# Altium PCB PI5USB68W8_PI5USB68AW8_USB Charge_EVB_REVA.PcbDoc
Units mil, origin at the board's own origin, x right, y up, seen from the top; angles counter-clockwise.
Board outline 2300 x 1200 mil, 4 copper layers (Top Layer, InternalPlane1, InternalPlane2, Bottom Layer); 16 components, 9 nets, 48 pads, 13 vias.
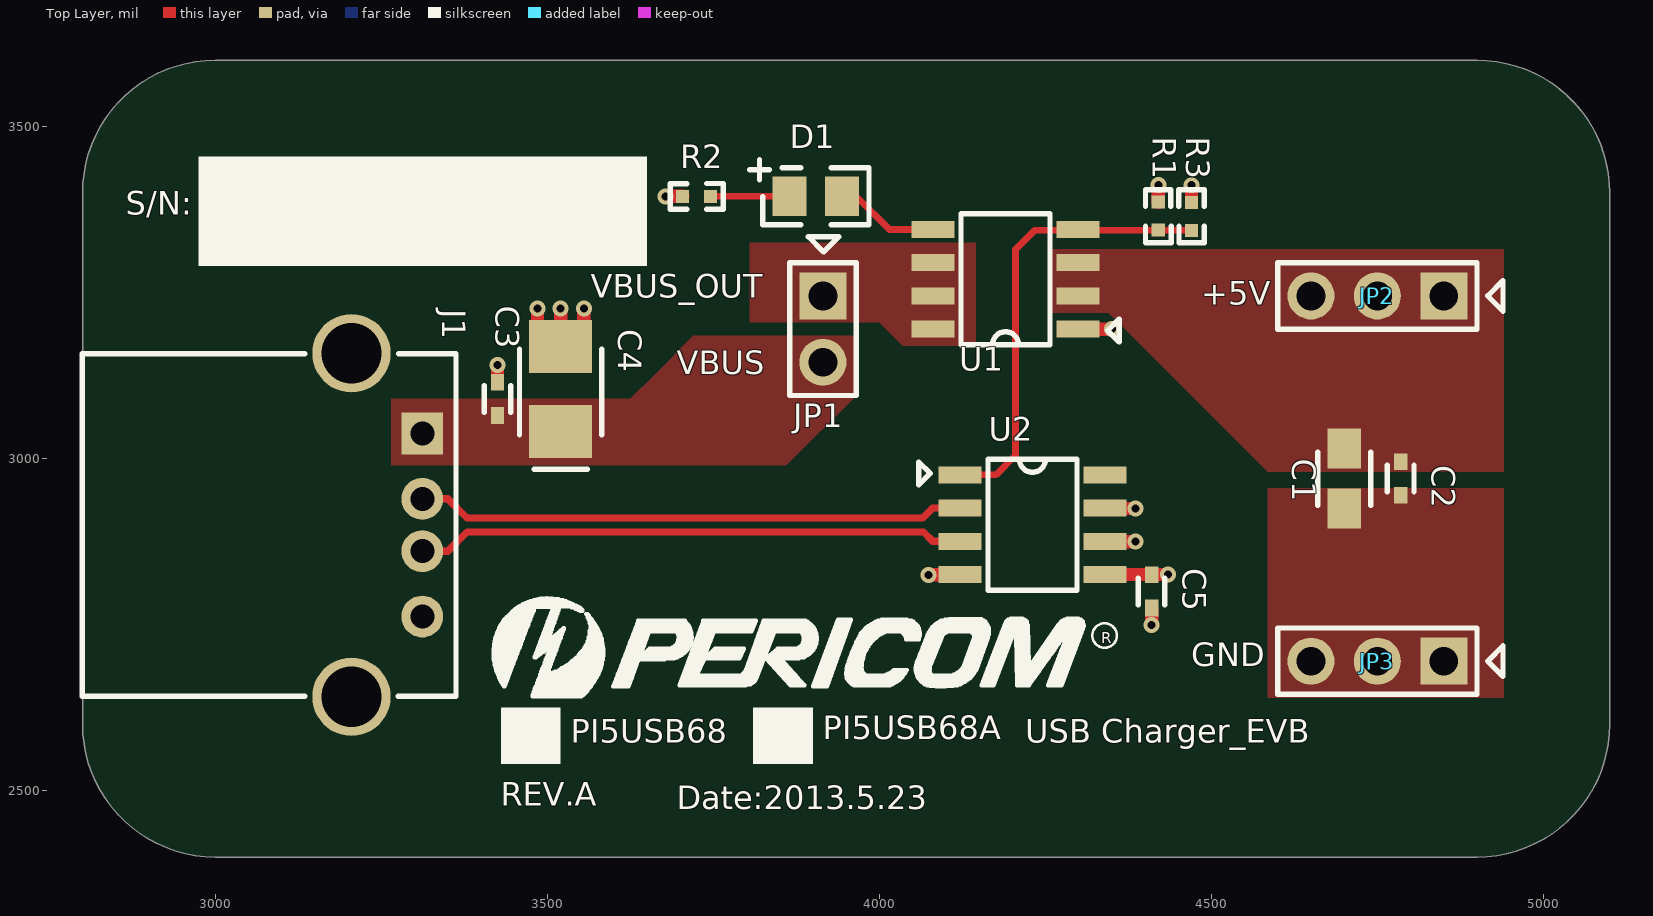
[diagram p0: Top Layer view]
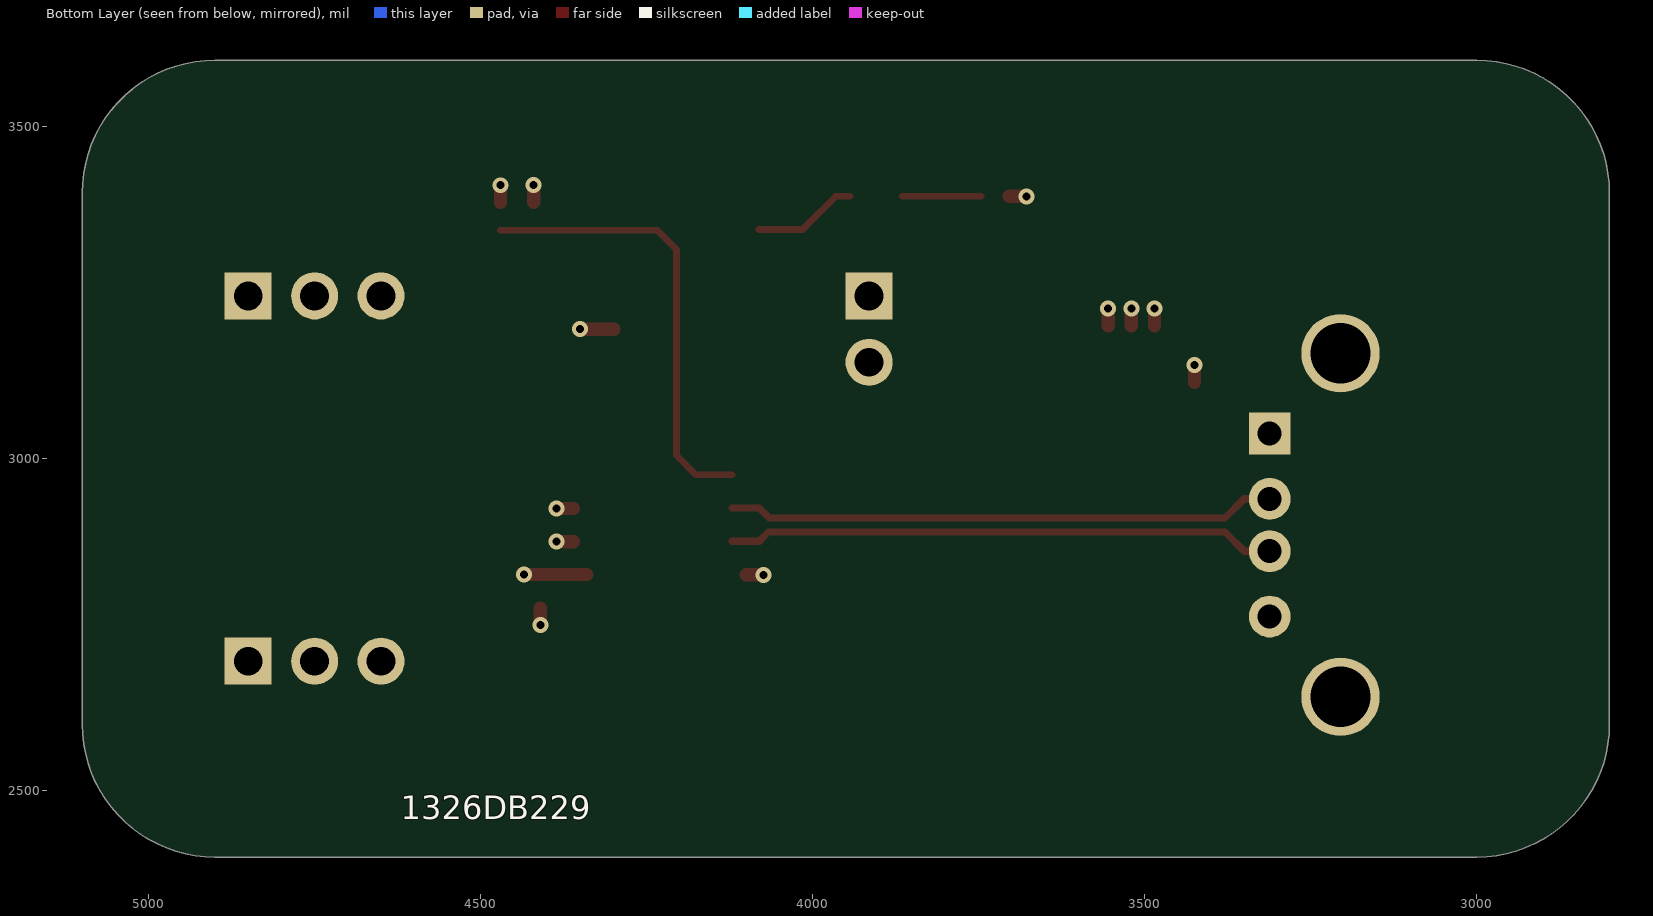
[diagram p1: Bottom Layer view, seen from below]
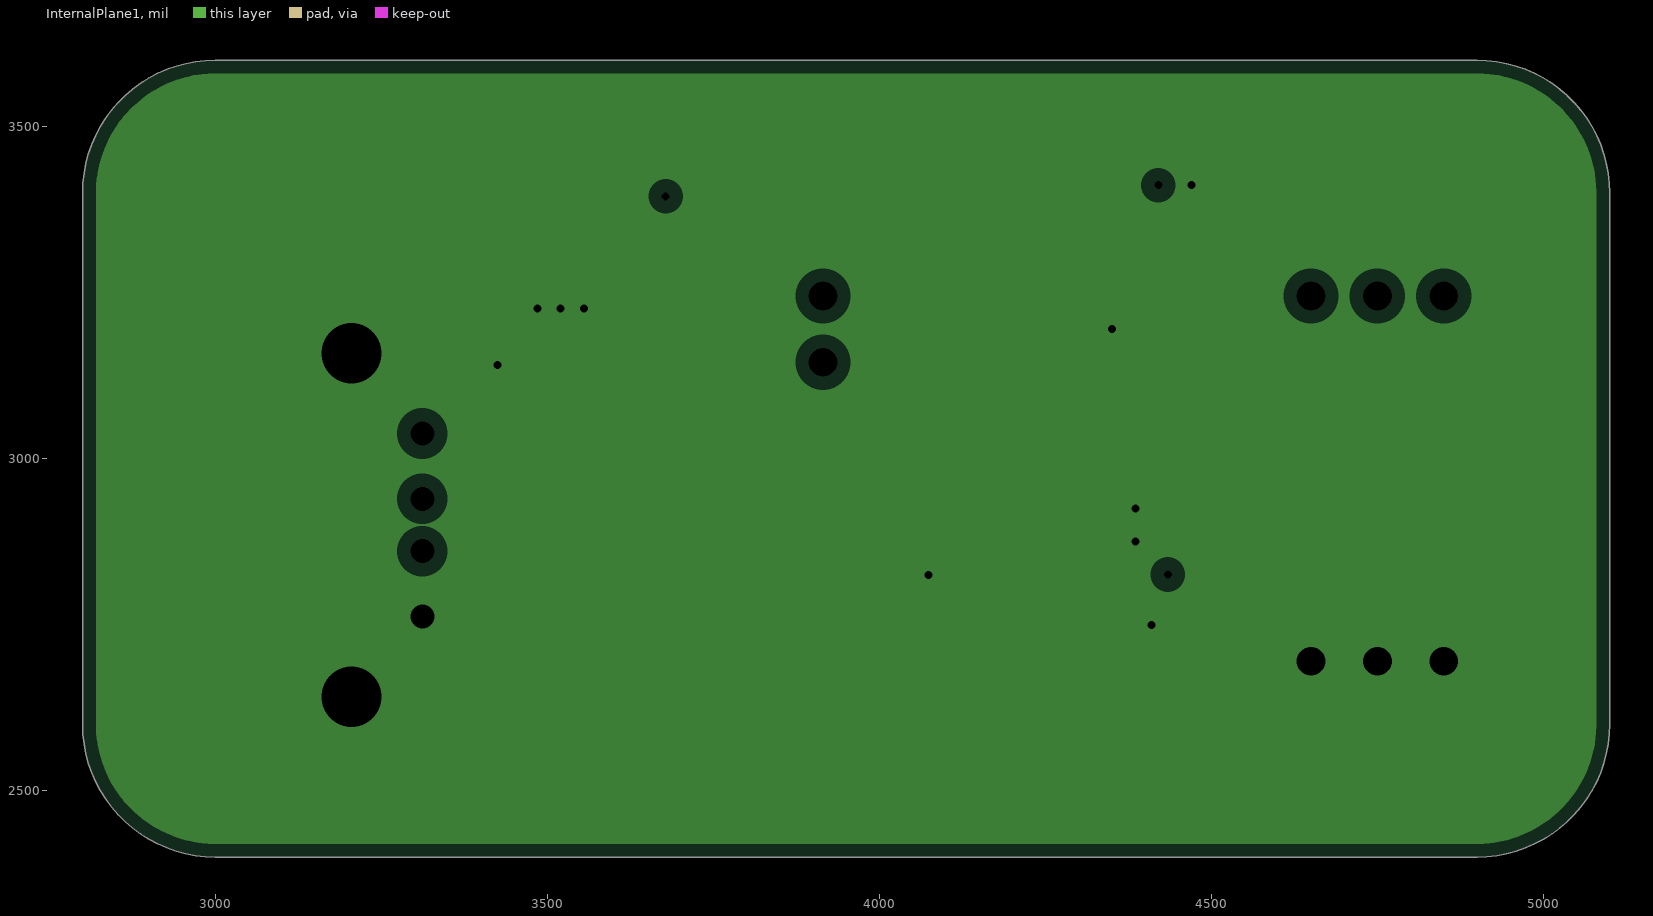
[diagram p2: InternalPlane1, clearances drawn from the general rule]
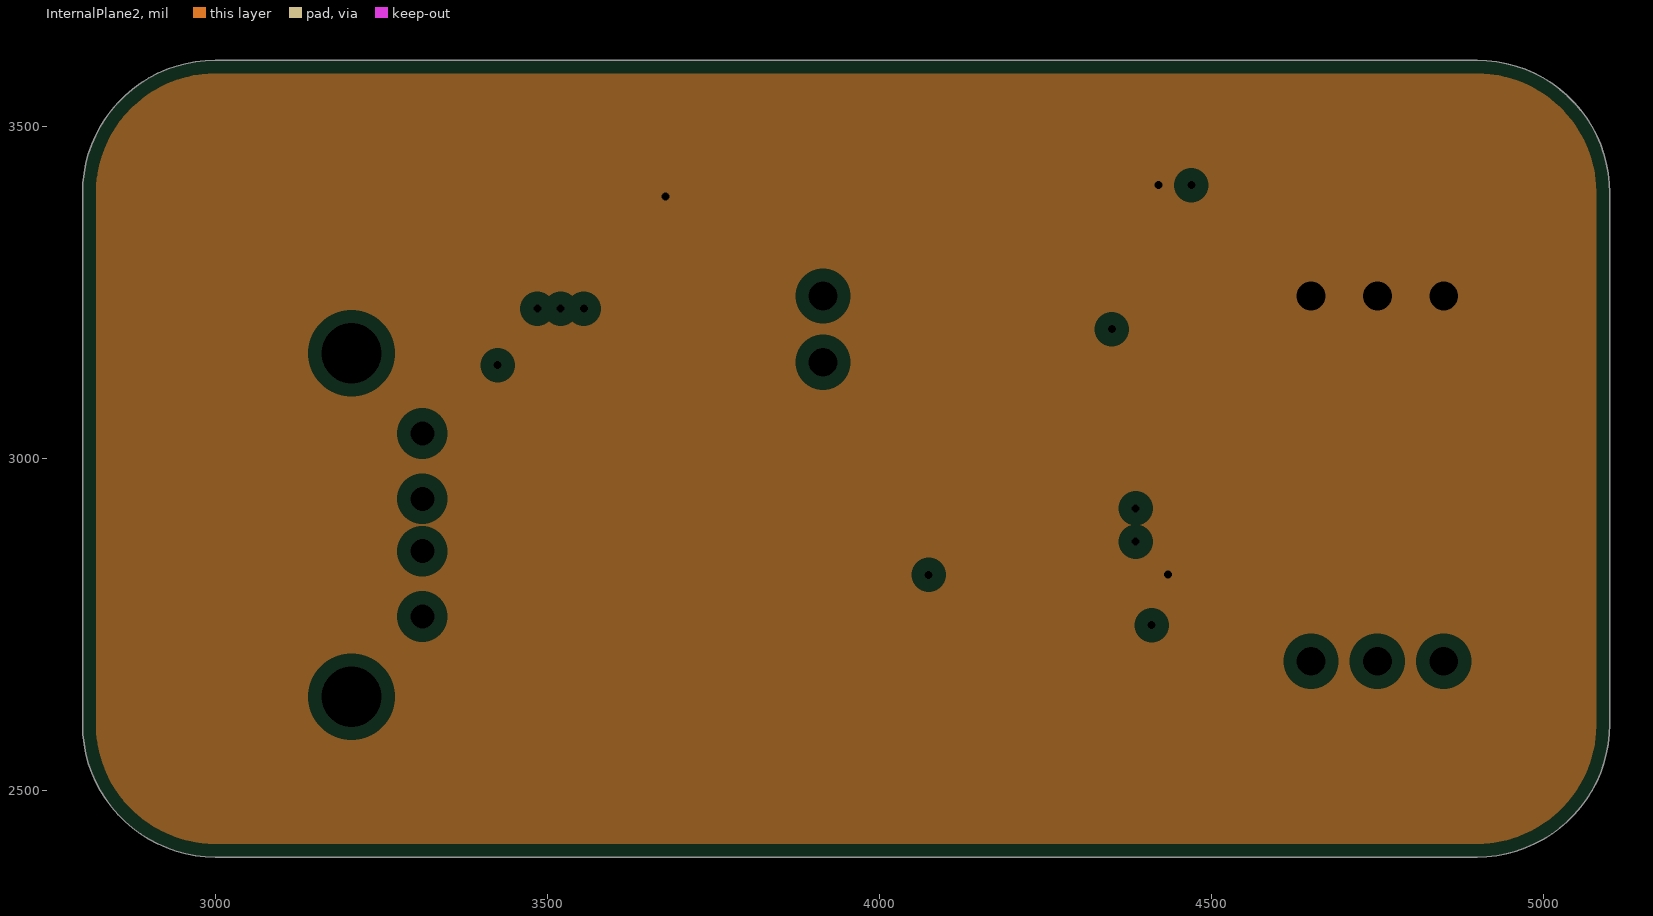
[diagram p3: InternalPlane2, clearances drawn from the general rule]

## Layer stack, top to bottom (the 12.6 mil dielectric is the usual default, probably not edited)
Top Layer: signal copper 1.4
Dielectric: core 12.6, FR-4, Dk 4.8
InternalPlane1: plane copper 1.4, net GND
Dielectric: prepreg 12.6, FR-4, Dk 4.8
InternalPlane2: plane copper 1.4, net +5V
Dielectric: core 12.6, FR-4, Dk 4.8
Bottom Layer: signal copper 1.4

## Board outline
2800,2600 2800,3400 cw(c3000,3400) 3000,3600 4900,3600 cw(c4900,3400) 5100,3400 5100,2600 cw(c4900,2600) 4900,2400 3000,2400 cw(c3000,2600)

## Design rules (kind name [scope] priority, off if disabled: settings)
Clearance [All] p1: gap=5
ComponentClearance [All] p1: gap=0 collisioncheckmode=3 verticalgap=0
DiffPairsRouting [All] p1: maxlimit=10 minlimit=10 mostfreqgap=10 maxuncoupledlength=500
HoleSize [All] p1: absolutevalues=TRUE maxlimit=550 minlimit=1 maxpercent=80.000 minpercent=20.000
PlaneClearance [All] p1: clearance=20
PlaneConnect [All] p1: planeconnectstyle=Direct reliefexpansion=20 reliefentries=4 reliefconductorwidth=10 reliefairgap=10
PolygonConnect [All] p1: connectstyle=Direct reliefconductorwidth=10 reliefentries=4 polygonreliefangle="90 Angle"
RoomDefinition "PI5USB68_PI5USB68A EVB" [InComponentClass('PI5USB68_PI5USB68A EVB ')] p1: confinementstyle=ConfineIn formatcopy=TRUE lockcomponents=FALSE outline 95,365 10600,365 10600,7605 95,7605
RoutingVias [All] p1: holewidth=28 width=50 viastyle="Through Hole" minholewidth=8 minwidth=10 maxholewidth=28 maxwidth=50
SolderMaskExpansion [All] p1: expansion=4
TestPointUsage [All] p1: valid=0 allowmultiple=FALSE
Testpoint [All] p1: side=15 testpointundercomponent=TRUE minsize=40 maxsize=100 preferedsize=60 minholesize=0 maxholesize=40 preferedholesize=32 testpointgrid=1 style=1023 order=0-112345678
Width [All] p1: maxlimit=150 minlimit=5 preferedwidth=10
14 further rules are at their usual default settings.

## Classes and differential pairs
component class "PI5USB68_PI5USB68A EVB": C1 C2 C3 C4 C5 D1 J1 JP1 JP2 JP3 R1 R2 R3 U1 U2
differential pair NewDifferentialPair1: +NetJ1_2 -NetJ1_3

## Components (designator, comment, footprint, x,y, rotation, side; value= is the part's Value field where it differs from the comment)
C1 "4.7uF" CC_0805 4700,2970 r270 top
C2 "0.1uF" CC_0402 4785,2970 r270 top
C3 "10n" CC_0402 3425,3090 r90 top
C4 "22u" CT_3528 3520,3105 r90 top
C5 "0.1uF" CAP@CC_0402 4410,2800 r270 top
D1 "LED_R" LED_0805 3904.37,3395 r0 top
J1 "CON_USB2.0_TA_Rec" CON_USB2.0_TA_Rec 3205,2900 r270 top
JP1 "2x1 Pin Header" "2x1 Pin Header" 3915,3245 r270 top
JP2 "3x1 Pin Header" "3x1 Pin Header" 4850,3245 r180 top
JP3 "3x1 Pin Header" "3x1 Pin Header" 4850,2695 r180 top
R1 "10k" R_0402 4420,3365 r90 top
R2 "560" R_0402 3725,3395 r180 top
R3 "10k" R_0402 4470,3365 r270 top
U1 "PI5PD2069 / PI5PD2068" SOIC8 4190,3270 r90 top
U2 "PI5USB68_PI5USB68A" SOIC8 4230.5,2900.5 r270 top
? "Comment" PSC_LOG 3525,2745 r0 top

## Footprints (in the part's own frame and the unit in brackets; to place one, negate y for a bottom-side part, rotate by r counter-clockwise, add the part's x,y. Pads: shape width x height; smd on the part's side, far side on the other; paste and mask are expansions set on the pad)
"2x1 Pin Header" [mm] "Pin Header 2x1 Pitch 2.54mm"
  rect 1.8x1.8 hole 1.1: 1(0,0)
  round 1.8 hole 1.1: 2(2.54,0)
  silkscreen extent -2.27,-1.27 3.81,1.27
"3x1 Pin Header" [mm] "Pin Header 3x1 Pitch 2.54mm"
  rect 1.8x1.8 / inner round 1.8 / far side rect 1.8x1.8 hole 1.1: 1(0,0)
  round 1.8 hole 1.1: 2(2.54,0) 3(5.08,0)
  silkscreen extent -2.27,-1.27 6.35,1.27
CAP@CC_0402 [mil]
  rect 25x20 smd: 1(-25,0) 2(25,0)
  silkscreen extent -20,-20 20,20
CC_0402 [mil]
  rect 25x20 smd: 1(-25,0) 2(25,0)
  silkscreen extent -20,-20 20,20
CC_0805 [mil]
  rect 60x50 smd: 1(-45,0) 2(45,0)
  silkscreen extent -40,-40 40,40
CON_USB2.0_TA_Rec [mm]
  rect 1.6x1.6 hole 0.92: 1(-3.5,2.71)
  round 1.6 hole 0.92: 2(-1,2.71) 3(1,2.71) 4(3.5,2.71)
  round 3 hole 2.3: 5(-6.57,0) 5(6.57,0)
  silkscreen extent -6.55,-10.3 6.55,4
CT_3528 [mil]
  rect 80x95 smd: 1(-64,0) 2(64,0)
  silkscreen extent -121,-62 60,62
LED_0805 [mm] "Chip Resistor; Body 2 x 1.3 mm (LxW typ)"
  rect 1.3x1.5 smd: 1(-1,0) 2(1,0)
  silkscreen extent -2.54,-1.09 2.03,1.4
PSC_LOG [mil]
  silkscreen extent -107,-103 833,45
R_0402 [mm]
  rect 0.5x0.5 smd: 1(-0.532,-0.001) 2(0.54,-0.001)
  silkscreen extent -1.02,-0.49 1.02,0.49
SOIC8 [mm]
  rect 0.65x1.65 smd: 1(-1.905,-2.775) 2(-0.635,-2.775) 3(0.635,-2.775) 4(1.905,-2.775) 5(1.905,2.775) 6(0.635,2.775) 7(-0.635,2.775) 8(-1.905,2.775)
  silkscreen extent -2.5,-4.35 2.5,1.7

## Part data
C1: library part C_4.7u_0805
C2 C5: library part C_4.7u_0805_Dup1
C3: library part C_10n_0402
C4: library part C_tan_22u_3528
D1: library part LED_0805_R
R1 R2 R3: library part R_0402
U1: library part PI90LV018A@SOIC8_0
U2: library part PI6C2405A-1WE@SOIC8_0

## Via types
v1: diameter 24, hole 12, Top Layer to Bottom Layer, tented both sides, 13 vias

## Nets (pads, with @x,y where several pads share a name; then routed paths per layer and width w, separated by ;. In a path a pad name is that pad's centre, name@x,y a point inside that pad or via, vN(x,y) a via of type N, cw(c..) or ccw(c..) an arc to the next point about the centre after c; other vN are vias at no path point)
+5V: C1.1 C2.1 C5.1 JP2.1 JP2.2 JP2.3 R1.2 R2.2 U1.2 U1.3 U2.5 | length 146.2
  Top Layer w20: v1(3677.98,3395.03) R2.2 ; U2.5 v1(4434.5,2825.5) ; R1.2 v1(4420.03,3412.02)
GND: C1.2 C2.2 C3.2 C4.2 C5.2 J1.4 J1.5 JP3.1 JP3.2 JP3.3 R3.1 U1.1 U2.4 U2.6 U2.7 | length 282.5
  Top Layer w20: C3.2 v1(3425,3140.75) ; C4.2@3485,3200 v1(3485,3225.75) ; C4.2@3520,3200 v1(3520,3225.75) ; C4.2@3555,3200 v1(3555,3225.75) ; v1(4074.25,2825) U2.4@4100,2825 ; U1.1 v1(4350,3195) ; U2.6@4360,2875 v1(4385.75,2875) ; U2.7@4360,2925 v1(4385.75,2925) ; v1(4410,2749.25) C5.2 ; R3.1 v1(4469.97,3411.7)
INT: R1.1 R3.2 U1.4 U2.1 | length 682.8
  Top Layer w10: U2.1 4175.5,2975.5 4205,3005 4205,3315 4233.73,3343.73 R3.2
NetD1_1: D1.1 R2.1 | length 119
  Top Layer w10: R2.1 D1.1
NetD1_2: D1.2 U1.5 | length 157.7
  Top Layer w10: D1.2 3965,3395 4015,3345 U1.5
NetJ1_2: J1.2 U2.2 | length 827.7
  Top Layer w11: J1.2 3350,2939.37 3378.87,2910.5 3790,2910.5 4065.5,2910.5 4080.5,2925.5 U2.2
NetJ1_3: J1.3 U2.3 | length 827.3
  Top Layer w11: J1.3 3350,2860.63 3378.87,2889.5 3790,2889.5 4066.5,2889.5 4080.5,2875.5 U2.3
VBUS: C3.1 C4.1 J1.1 JP1.2
VBUS_OUT: JP1.1 U1.6 U1.7 U1.8
pads on no net: U2.8

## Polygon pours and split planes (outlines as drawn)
VBUS on Top Layer "Bottom Layer-No Net" (solid, remove dead copper, pour order 1000): 3265,2990 3860,2990 3965,3095 3965,3180 3965,3185 3720,3185 3660,3125 3625,3090 3390,3090 3265,3090 3265,2990
VBUS_OUT on Top Layer "Bottom Layer-No Net" (solid, remove dead copper, pour order 1001): 3805,3325 4145,3325 4145,3170 4035,3170 4000,3205 3805,3205 3805,3325
GND on Top Layer "Bottom Layer-No Net" (solid, remove dead copper, pour order 1002): 4585,2955 4585,2640 4940,2640 4940,2955 4585,2955
+5V on Top Layer "Bottom Layer-No Net" (solid, remove dead copper, pour order 1003): 4255,3315 4940,3315 4940,2980 4585,2980 4345,3220 4255,3220 4255,3315
GND on InternalPlane1 (split plane): 3000,3579.61 4900,3579.61 4901.05,3579.82 4923.48,3578.35 4946.56,3573.76 4968.84,3566.19 4989.94,3555.78 5009.51,3542.71 5027.2,3527.2 5042.71,3509.51 5055.79,3489.94 5066.19,3468.84 5073.76,3446.56 5078.35,3423.48 5079.82,3401.05 5079.61,3400 5079.61,2600 5079.82,2598.95 5078.35,2576.52 5073.76,2553.44 5066.19,2531.16 5055.79,2510.06 5042.71,2490.49 5027.2,2472.8 5009.51,2457.29 4989.94,2444.21 4968.84,2433.81 4946.56,2426.24 4923.48,2421.65 4901.05,2420.18 4900,2420.39 3000,2420.39 2998.95,2420.18 2976.52,2421.65 2953.44,2426.24 2931.16,2433.81 2910.06,2444.21 2890.49,2457.29 2872.8,2472.8 2857.29,2490.49 2844.22,2510.06 2833.81,2531.16 2826.24,2553.44 2821.65,2576.52 2820.18,2598.95 2820.39,2600 2820.39,3400 2820.18,3401.05 2821.65,3423.48 2826.24,3446.56 2833.81,3468.84 2844.21,3489.94 2857.29,3509.51 2872.8,3527.2 2890.49,3542.71 2910.06,3555.78 2931.16,3566.19 2953.44,3573.76 2976.52,3578.35 2998.95,3579.82
+5V on InternalPlane2 (split plane): 3000,3579.61 4900,3579.61 4901.05,3579.82 4923.48,3578.35 4946.56,3573.76 4968.84,3566.19 4989.94,3555.78 5009.51,3542.71 5027.2,3527.2 5042.71,3509.51 5055.79,3489.94 5066.19,3468.84 5073.76,3446.56 5078.35,3423.48 5079.82,3401.05 5079.61,3400 5079.61,2600 5079.82,2598.95 5078.35,2576.52 5073.76,2553.44 5066.19,2531.16 5055.79,2510.06 5042.71,2490.49 5027.2,2472.8 5009.51,2457.29 4989.94,2444.21 4968.84,2433.81 4946.56,2426.24 4923.48,2421.65 4901.05,2420.18 4900,2420.39 3000,2420.39 2998.95,2420.18 2976.52,2421.65 2953.44,2426.24 2931.16,2433.81 2910.06,2444.21 2890.49,2457.29 2872.8,2472.8 2857.29,2490.49 2844.22,2510.06 2833.81,2531.16 2826.24,2553.44 2821.65,2576.52 2820.18,2598.95 2820.39,2600 2820.39,3400 2820.18,3401.05 2821.65,3423.48 2826.24,3446.56 2833.81,3468.84 2844.21,3489.94 2857.29,3509.51 2872.8,3527.2 2890.49,3542.71 2910.06,3555.78 2931.16,3566.19 2953.44,3573.76 2976.52,3578.35 2998.95,3579.82

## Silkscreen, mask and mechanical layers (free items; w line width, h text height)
Top Overlay:
  rectangle: 3430,2540 3520,2625
  rectangle: 3810,2540 3900,2625
  rectangle: 2975,3290 3650,3455
  text "S/N:" at 2865,3355 h60
  text "VBUS_OUT" at 3565,3230 h60
  text "+5V" at 4485,3220 h60
  text "VBUS" at 3695,3115 h60
  text "GND" at 4470,2675 h60
  text "PI5USB68A" at 3915,2565 h60
  text "PI5USB68" at 3535,2560 h60
  text "USB Charger_EVB" at 4220,2560 h60
  text "REV.A" at 3430,2465 h60
  text "Date:2013.5.23" at 3695,2460 h60
Bottom Overlay:
  text "1326DB229" at 4620,2445 h60
Mechanical 1:
  the board outline again, w8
